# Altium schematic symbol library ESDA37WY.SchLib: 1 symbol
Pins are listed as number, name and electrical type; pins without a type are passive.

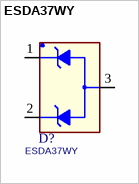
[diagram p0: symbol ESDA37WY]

## ESDA37WY
designator D?
footprint ST_SOT323-3L
pins: 1 K1, 2 K2, 3 A1A2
